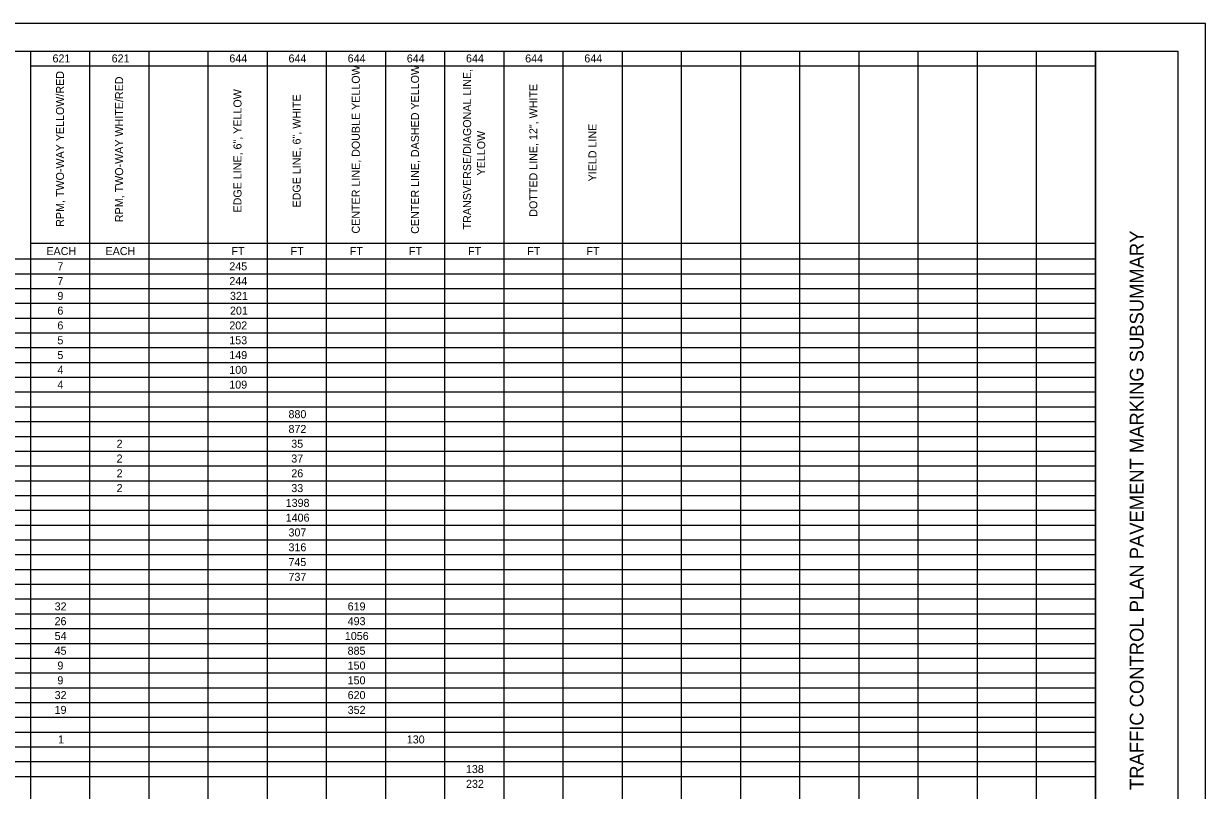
# Model space of a CAD drawing. Extents: x 0 to 34, y 0 to 22.
# Drawn here: x 12.5 to 34, y 8.05 to 22 of the extents above; entities that cross this region are included whole.
import ezdxf

# ---------------------------------------------------------------- set-up
doc = ezdxf.new("R2010")
doc.units = 0
for name, color, linetype in [('SH_Border', 7, 'Continuous'), ('SH_Cut_Line', 7, 'Continuous'), ('SH_Data', 7, 'Continuous'), ('SH_Text', 7, 'Continuous')]:
    doc.layers.add(name, color=color, linetype=linetype)

msp = doc.modelspace()

# ---------------------------------------------------------------- linework, layer by layer
at = {"layer": 'SH_Border'}
msp.add_line((32, 0.5), (32, 21.5), dxfattribs=at)
msp.add_lwpolyline([(1.5, 21.5), (33.5, 21.5), (33.5, 0.5), (1.5, 0.5)], close=True, dxfattribs=at)
at = {"layer": 'SH_Cut_Line'}
msp.add_lwpolyline([(0, 0), (34, 0), (34, 22), (0, 22)], close=True, dxfattribs=at)
at = {"layer": 'SH_Text'}
for p, q in [((1.5, 21.501), (32, 21.501)), ((12.627, 21.501), (12.627, 0.498)), ((13.703, 21.501), (13.703, 0.767)), ((14.779, 21.501), (14.779, 0.498)), ((15.856, 21.501), (15.856, 0.498)), ((16.932, 21.501), (16.932, 0.767)), ((18.008, 21.501), (18.008, 0.498)), ((19.085, 21.501), (19.085, 0.767)), ((20.161, 21.501), (20.161, 0.498)), ((21.237, 21.501), (21.237, 0.498)), ((22.313, 21.501), (22.313, 0.498)), ((23.39, 21.501), (23.39, 0.498)), ((24.466, 21.501), (24.466, 0.498)), ((25.542, 21.501), (25.542, 0.498)), ((26.619, 21.501), (26.619, 0.498)), ((27.695, 21.501), (27.695, 0.498)), ((28.771, 21.501), (28.771, 0.498)), ((29.847, 21.501), (29.847, 0.498)), ((30.924, 21.501), (30.924, 0.498)), ((32, 21.501), (32, 0.498)), ((12.627, 21.232), (32, 21.232)), ((12.627, 18.003), (32, 18.003)), ((1.5, 17.718), (32, 17.718)), ((1.5, 17.449), (32, 17.449)), ((1.5, 17.18), (32, 17.18)), ((1.5, 16.911), (32, 16.911)), ((1.5, 16.642), (32, 16.642)), ((1.5, 16.373), (32, 16.373)), ((1.5, 16.104), (32, 16.104)), ((1.5, 15.835), (32, 15.835)), ((1.5, 15.566), (32, 15.566)), ((1.5, 15.297), (32, 15.297)), ((1.5, 15.027), (32, 15.027)), ((1.5, 14.758), (32, 14.758)), ((1.5, 14.489), (32, 14.489)), ((1.5, 14.22), (32, 14.22)), ((1.5, 13.951), (32, 13.951)), ((1.5, 13.682), (32, 13.682)), ((1.5, 13.413), (32, 13.413)), ((1.5, 13.144), (32, 13.144)), ((1.5, 12.875), (32, 12.875)), ((1.5, 12.606), (32, 12.606)), ((1.5, 12.337), (32, 12.337)), ((1.5, 12.068), (32, 12.068)), ((1.5, 11.799), (32, 11.799)), ((1.5, 11.53), (32, 11.53)), ((1.5, 11.26), (32, 11.26)), ((1.5, 10.991), (32, 10.991)), ((1.5, 10.722), (32, 10.722)), ((1.5, 10.453), (32, 10.453)), ((1.5, 10.184), (32, 10.184)), ((1.5, 9.915), (32, 9.915)), ((1.5, 9.646), (32, 9.646)), ((1.5, 9.377), (32, 9.377)), ((1.5, 9.108), (32, 9.108)), ((1.5, 8.839), (32, 8.839)), ((1.5, 8.57), (32, 8.57)), ((1.5, 8.301), (32, 8.301))]:
    msp.add_line(p, q, dxfattribs=at)

# ---------------------------------------------------------------- texts
at = {"layer": 'SH_Data'}
msp.add_text('TRAFFIC CONTROL PLAN PAVEMENT MARKING SUBSUMMARY', height=0.25, rotation=90, dxfattribs=at).set_placement((32.875, 8.055))
at = {"layer": 'SH_Text'}
for s, height, p in [('621', 0.1456, (13.029, 21.294)), ('621', 0.1456, (14.105, 21.294)), ('644', 0.1456, (16.246, 21.294)), ('644', 0.1456, (17.322, 21.294)), ('644', 0.1456, (18.398, 21.294)), ('644', 0.1456, (19.474, 21.294)), ('644', 0.1456, (20.551, 21.294)), ('644', 0.1456, (21.627, 21.294)), ('644', 0.1456, (22.703, 21.294)), ('EACH', 0.1456, (12.918, 17.788)), ('EACH', 0.1456, (13.994, 17.788)), ('FT', 0.1456, (16.284, 17.788)), ('FT', 0.1456, (17.36, 17.788)), ('FT', 0.1456, (18.436, 17.788)), ('FT', 0.1456, (19.513, 17.788)), ('FT', 0.1456, (20.589, 17.788)), ('FT', 0.1456, (21.665, 17.788)), ('FT', 0.1456, (22.742, 17.788)), ('7', 0.146, (13.118, 17.511)), ('245', 0.1456, (16.245, 17.511)), ('7', 0.146, (13.118, 17.242)), ('244', 0.1456, (16.246, 17.242)), ('9', 0.146, (13.118, 16.973)), ('321', 0.1456, (16.258, 16.973)), ('6', 0.146, (13.118, 16.704)), ('201', 0.1456, (16.258, 16.704)), ('6', 0.146, (13.118, 16.435)), ('202', 0.1456, (16.246, 16.435)), ('5', 0.146, (13.118, 16.165)), ('153', 0.1456, (16.245, 16.165)), ('5', 0.146, (13.118, 15.896)), ('149', 0.1456, (16.245, 15.896)), ('4', 0.146, (13.119, 15.627)), ('100', 0.1456, (16.246, 15.627)), ('4', 0.146, (13.119, 15.358)), ('109', 0.1456, (16.245, 15.358)), ('880', 0.1456, (17.322, 14.82)), ('872', 0.1456, (17.322, 14.551)), ('2', 0.146, (14.195, 14.282)), ('35', 0.1456, (17.372, 14.282)), ('2', 0.146, (14.195, 14.013)), ('37', 0.1456, (17.373, 14.013)), ('2', 0.146, (14.195, 13.744)), ('26', 0.1456, (17.373, 13.744)), ('2', 0.146, (14.195, 13.475)), ('33', 0.1456, (17.373, 13.475)), ('1398', 0.1456, (17.271, 13.206)), ('1406', 0.1456, (17.271, 12.937)), ('307', 0.1456, (17.322, 12.668)), ('316', 0.1456, (17.322, 12.398)), ('745', 0.1456, (17.321, 12.129)), ('737', 0.1456, (17.322, 11.86)), ('32', 0.1456, (13.068, 11.322)), ('619', 0.1456, (18.398, 11.322)), ('26', 0.1456, (13.067, 11.053)), ('493', 0.1456, (18.398, 11.053)), ('54', 0.1456, (13.068, 10.784)), ('1056', 0.1456, (18.347, 10.784)), ('45', 0.1456, (13.067, 10.515)), ('885', 0.1456, (18.397, 10.515)), ('9', 0.146, (13.118, 10.246)), ('150', 0.1456, (18.398, 10.246)), ('9', 0.146, (13.118, 9.977)), ('150', 0.1456, (18.398, 9.977)), ('32', 0.1456, (13.068, 9.708)), ('620', 0.1456, (18.398, 9.708)), ('19', 0.1456, (13.067, 9.439)), ('352', 0.1456, (18.399, 9.439)), ('1', 0.146, (13.131, 8.901)), ('130', 0.1456, (19.474, 8.901)), ('138', 0.1456, (20.55, 8.362)), ('232', 0.1456, (20.551, 8.093))]:
    msp.add_text(s, height=height, dxfattribs=at).set_placement(p)
for s, height, p in [('RPM, TWO-WAY YELLOW/RED', 0.14561, (13.238, 18.303)), ('CENTER LINE, DOUBLE YELLOW', 0.14561, (18.619, 18.18)), ('CENTER LINE, DASHED YELLOW', 0.14561, (19.696, 18.175)), ('TRANSVERSE/DIAGONAL LINE, ', 0.14561, (20.644, 18.255)), ('RPM, TWO-WAY WHITE/RED', 0.14561, (14.314, 18.388)), ('DOTTED LINE, 12", WHITE', 0.14561, (21.848, 18.486)), ('EDGE LINE, 6", YELLOW', 0.14561, (16.467, 18.563)), ('EDGE LINE, 6", WHITE', 0.14561, (17.543, 18.654)), ('YELLOW', 0.1456, (20.899, 19.237)), ('YIELD LINE', 0.1456, (22.924, 19.129))]:
    msp.add_text(s, height=height, rotation=90, dxfattribs=at).set_placement(p)

doc.saveas('drawing.dxf')
